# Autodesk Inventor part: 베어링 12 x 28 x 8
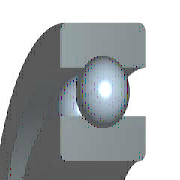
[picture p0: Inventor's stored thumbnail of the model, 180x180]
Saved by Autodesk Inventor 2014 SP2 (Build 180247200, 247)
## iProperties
IsCustomPart: 1
Created: 2012-02
Part Number: 베어링 12 x 28 x 8
Material: 강철, 연강
Description: 깊은 그루브 볼 베어링
Document SubType Name: Modeling
Standard: KS B 2023
Designer: mduedu
Standards Organization: KS
Language: ko-KR
Size Designation: 6001 - 12 x 28 x 8
Categories: <MemberInstance><Categories><Category DisplayName="샤프트 부품" InternalName="7f7aeb1f-a693-4053-b835-cee3144e0d98" Mnemonic="SHFT"><Category DisplayName="베어링" Inter
Density: 7.86 g/cm^3
Appearance: 노란색
Mass: 21.4854 g
Surface Area: 31.1809 cm^2
Volume: 2.73351 cm^3
Author: mduedu
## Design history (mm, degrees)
sketch "스케치" dims "d0" = 4.16 (= -0.26 x WD + 0.26 x BD)
  geometry: L1 (1.92, 10)-(6.08, 10); L2 (4, 10)-(4, 7.92); L3 (4, 10)-(4, 12.08); L4 (2.454, 8.608)-(0, 8.608); L5 (0, 6)-(8, 6); L6 (2.454, 11.392)-(0, 11.392); L7 (0, 14)-(8, 14); L8 (8, 6)-(8, 8.608); L9 (5.546, 8.608)-(8, 8.608); L10 (5.546, 11.392)-(8, 11.392); L11 (8, 14)-(8, 11.392); L12 (-1.4, 0)-(8.4, 0) reference; L13 (0, -0.3)-(0, 5.3) reference
  constraints: 22 end point, 4 point on line, 2 collinear, 2 perpendicular, 2 symmetric about line, 1 midpoint, 1 parallel, 14 other
  dimensions: "d9" = 12 diameter of L5 L12 (= WD); "d11" = 28 diameter of L7 L12 (= BD); "d12" = 8 distance between parallel lines of L8 L13 (= KB); "d13" = 17.216 diameter of L9 L12 (= 0.326 x BD + 0.674 x WD)
revolve "본체" stored, may be unused: angle "d6" = 90 deg
revolve "볼" stored, may be unused: angle "d7" = 90 deg
pattern_circular "IDS_ARRAYBALL[SIMPL:T]" dims angle "d3" = 360 deg
body "Solid1"
fillet "모깎기1" dims "d1" = 0.3 (= KRS)
other parameters: "WD" = 12 [user parameter; used in 5 equation terms], "BD" = 28 [user parameter; used in 5 equation terms], "KB" = 8 [user parameter; used in 1 equation term], "KRS" = 0.3 [user parameter; used in 1 equation term], "d4" = 0, "d5" = 0, "d8" = 0, "d14" = 0, "d15" = 0, "BBA" = 0 [user parameter], "BC0" = 2360000 [user parameter], "BC" = 5070000 [user parameter], "BR" = 14 (= 0.5 x BD) [user parameter], "WR" = 6 (= 0.5 x WD) [user parameter]
